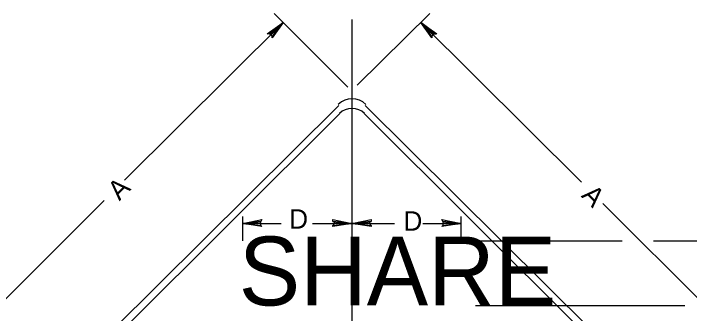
# Model space of a CAD drawing. Extents: x -0.018 to 0.195, y -0.006 to 0.263.
# Drawn here: x 0.0462 to 0.1297, y 0.1654 to 0.2025 of the extents above; entities that cross this region are included whole.
import ezdxf

# ---------------------------------------------------------------- set-up
doc = ezdxf.new("R2010")
doc.units = 0
doc.layers.add('1', color=7, linetype='Continuous')
doc.layers.add('12', color=7, linetype='Continuous')

msp = doc.modelspace()

# ---------------------------------------------------------------- linework, layer by layer
at = {"layer": '1'}
for p, q in [((0.078375, 0.2025), (0.0875, 0.193375)), ((0.088625, 0.193625), (0.097625, 0.2025)), ((0.059875, 0.181875), (0.0795, 0.201375)), ((0.088, 0.20175), (0.088, 0.10525)), ((0.0965, 0.201375), (0.116375, 0.181625)), ((0.037, 0.159), (0.057375, 0.179375)), ((0.119, 0.179), (0.139, 0.159)), ((0.12525, 0.174375), (0.143, 0.174375)), ((0.10325, 0.166375), (0.129125, 0.166375))]:
    msp.add_line(p, q, dxfattribs=at)
for points in [[(0.07775, 0.2), (0.077875, 0.2), (0.0795, 0.201375), (0.07775, 0.2), (0.0775, 0.2), (0.0795, 0.201375), (0.078, 0.199875), (0.078125, 0.199625), (0.0795, 0.201375), (0.078125, 0.1995), (0.078125, 0.199625)], [(0.097875, 0.199625), (0.098, 0.199875), (0.0965, 0.201375), (0.097875, 0.199625), (0.097875, 0.1995), (0.0965, 0.201375), (0.098125, 0.2), (0.098375, 0.2), (0.0965, 0.201375), (0.0985, 0.2), (0.098375, 0.2)]]:
    msp.add_lwpolyline(points, dxfattribs=at)
at = {"layer": '12'}
for p, q in [((0.04725, 0.15225), (0.086375, 0.191125)), ((0.089625, 0.191125), (0.12875, 0.15225)), ((0.048375, 0.152125), (0.0865, 0.190125)), ((0.0895, 0.190125), (0.127625, 0.152125)), ((0.0745, 0.174375), (0.0745, 0.177375)), ((0.1015, 0.17475), (0.1015, 0.177375)), ((0.0745, 0.1765), (0.07925, 0.1765)), ((0.083125, 0.1765), (0.088, 0.1765)), ((0.088, 0.1765), (0.09325, 0.1765)), ((0.09675, 0.1765), (0.1015, 0.1765)), ((0.10325, 0.174375), (0.121375, 0.174375))]:
    msp.add_line(p, q, dxfattribs=at)
for points in [[(0.07675, 0.17625), (0.07675, 0.1765), (0.0745, 0.1765), (0.07675, 0.17625), (0.076875, 0.176125), (0.0745, 0.1765), (0.07675, 0.176625), (0.07675, 0.17675), (0.0745, 0.1765), (0.076875, 0.177), (0.07675, 0.17675)], [(0.085625, 0.17675), (0.085875, 0.176625), (0.088, 0.1765), (0.085625, 0.17675), (0.085625, 0.177), (0.088, 0.1765), (0.085875, 0.1765), (0.085625, 0.17625), (0.088, 0.1765), (0.085625, 0.176125), (0.085625, 0.17625)], [(0.090375, 0.17625), (0.090125, 0.1765), (0.088, 0.1765), (0.090375, 0.17625), (0.090375, 0.176125), (0.088, 0.1765), (0.090125, 0.176625), (0.090375, 0.17675), (0.088, 0.1765), (0.090375, 0.177), (0.090375, 0.17675)], [(0.09925, 0.17675), (0.09925, 0.176625), (0.1015, 0.1765), (0.09925, 0.17675), (0.099125, 0.177), (0.1015, 0.1765), (0.09925, 0.1765), (0.09925, 0.17625), (0.1015, 0.1765), (0.099125, 0.176125), (0.09925, 0.17625)]]:
    msp.add_lwpolyline(points, dxfattribs=at)
for centre, radius in [((0.088006, 0.189548), 0.0024), ((0.088006, 0.188559), 0.0022)]:
    msp.add_arc(centre, radius, 45, 135, dxfattribs=at)

# ---------------------------------------------------------------- texts
at = {"layer": '1'}
msp.add_text('A', height=0.002399, rotation=45, dxfattribs=at).set_placement((0.05925, 0.17925))
at = {"layer": '12'}
msp.add_text('A', height=0.002399, rotation=315, dxfattribs=at).set_placement((0.11625, 0.179875))
for s, height, p in [('D', 0.002399, (0.08025, 0.175875)), ('D', 0.002399, (0.094375, 0.175625)), ('SHARE', 0.008517, (0.074, 0.166375))]:
    msp.add_text(s, height=height, dxfattribs=at).set_placement(p)

doc.saveas('drawing.dxf')
